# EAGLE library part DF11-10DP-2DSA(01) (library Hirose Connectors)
CONN, VERT, PTH, 10 POS, 5x2, 2mm PITCH, GOLD (HIROSE)
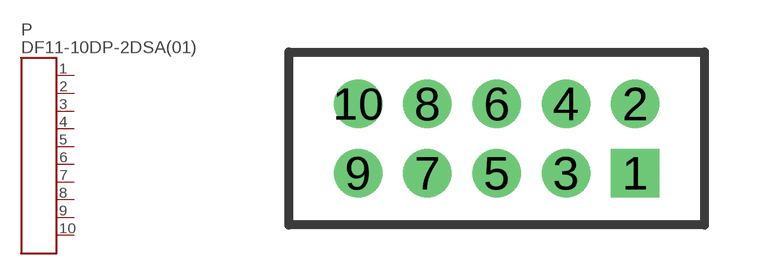
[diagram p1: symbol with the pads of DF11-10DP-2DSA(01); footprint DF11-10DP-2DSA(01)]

Designator prefix P

## DF11-10DP-2DSA(01)  [DF11-10DP-2DSA(01)]
1  P$1
2  P$2
3  P$3
4  P$4
5  P$5
6  P$6
7  P$7
8  P$8
9  P$9
10  P$10

## Footprint DF11-10DP-2DSA(01) (pad centres in mm)
drill 0.889 pad 1.27 square: 1 4,-1
drill 0.889 pad 1.27 round: 2 4,1; 3 2,-1; 4 2,1; 5 0,-1; 6 0,1; 7 -2,-1; 8 -2,1; 9 -4,-1; 10 -4,1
